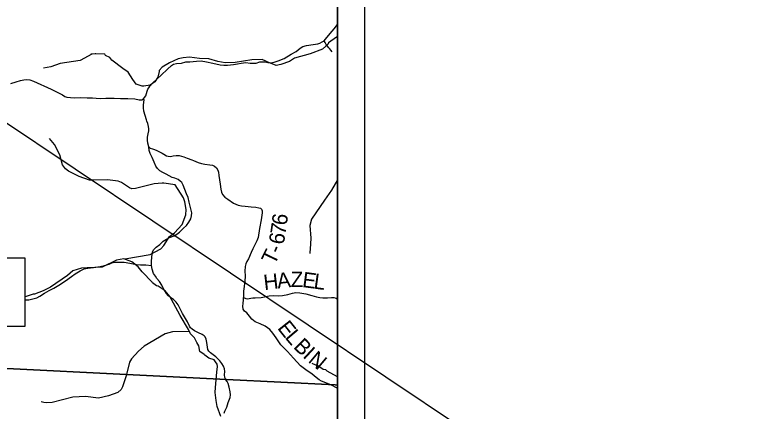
# Model space of a CAD drawing. Extents: x -1.8 to 75.7, y -2 to 25.
# Drawn here: x 7.704 to 10.399, y 16.93 to 18.399 of the extents above; entities that cross this region are included whole.
import ezdxf

# ---------------------------------------------------------------- set-up
doc = ezdxf.new("R2010")
doc.units = 0
for name, color, linetype in [('GM_X_County_Road', 7, 'Continuous'), ('GM_X_Minor_River', 7, 'Continuous'), ('GM_X_Township', 7, 'Continuous'), ('GM_X_Township_Road', 7, 'Continuous'), ('GM_X_Township_Road_Text', 7, 'Continuous'), ('SH_Data', 7, 'Continuous'), ('TX_P_1', 7, 'Continuous')]:
    doc.layers.add(name, color=color, linetype=linetype)

msp = doc.modelspace()

# ---------------------------------------------------------------- linework, layer by layer
at = {"layer": 'GM_X_County_Road'}
for points in [[(7.6901, 18.1441), (7.7101, 18.1505), (7.7266, 18.1554), (7.7386, 18.1583), (7.7495, 18.1594), (7.761, 18.1577), (7.774, 18.1524), (7.8395, 18.1227), (7.8649, 18.1103), (7.8814, 18.1017), (7.8905, 18.0962), (7.8982, 18.0935), (7.9118, 18.0918), (7.927, 18.0914), (7.95, 18.0925), (7.9735, 18.0912), (7.9924, 18.0916), (8.0071, 18.0897), (8.0216, 18.0889), (8.0419, 18.0895), (8.0599, 18.0893), (8.0732, 18.0896), (8.0962, 18.0887), (8.1235, 18.0882), (8.1497, 18.087), (8.1656, 18.0839), (8.1753, 18.0832), (8.1821, 18.0868), (8.186, 18.0917), (8.19, 18.0987), (8.1958, 18.1153), (8.1984, 18.1232), (8.2012, 18.1282), (8.2049, 18.1342), (8.2162, 18.1462), (8.247, 18.1755), (8.27, 18.1976), (8.2854, 18.2109), (8.2927, 18.2154), (8.3044, 18.2182), (8.3224, 18.22), (8.3383, 18.2238), (8.3538, 18.2243), (8.3779, 18.2273), (8.395, 18.2286), (8.4152, 18.2243), (8.4389, 18.2191), (8.466, 18.2135), (8.4791, 18.2118), (8.493, 18.2124), (8.5147, 18.2139), (8.5296, 18.2165), (8.5438, 18.2199), (8.5607, 18.2214), (8.5771, 18.2199), (8.5902, 18.2191), (8.5988, 18.22), (8.6125, 18.2242), (8.6213, 18.2249), (8.6314, 18.224), (8.6426, 18.2215), (8.6533, 18.2204), (8.6654, 18.2228), (8.6802, 18.2283), (8.7026, 18.2371), (8.729, 18.2522), (8.7464, 18.2629), (8.7616, 18.2754), (8.7715, 18.2812), (8.7849, 18.2849), (8.8094, 18.2881), (8.8276, 18.2913), (8.8349, 18.2935), (8.8433, 18.2978), (8.8508, 18.3023), (8.8554, 18.3078), (8.8725, 18.3289), (8.8874, 18.3469), (8.9, 18.3629)], [(8.2016, 17.9093), (8.1978, 17.9228), (8.1961, 17.934), (8.1971, 17.945), (8.1992, 17.9573), (8.2009, 17.9685), (8.2013, 17.9768), (8.2001, 17.9844), (8.1984, 17.9954), (8.1944, 18.0045), (8.1925, 18.0096), (8.1876, 18.0256), (8.1829, 18.0417), (8.1812, 18.0542), (8.1817, 18.0644), (8.1831, 18.075), (8.184, 18.0834), (8.1821, 18.0868)], [(8.2749, 17.3575), (8.2746, 17.3577), (8.2665, 17.3668), (8.2613, 17.3758), (8.2551, 17.3867), (8.2493, 17.3969), (8.2408, 17.4104), (8.2312, 17.4226), (8.2257, 17.4301), (8.2187, 17.4407), (8.2137, 17.4566), (8.2109, 17.4696), (8.2113, 17.4861), (8.2134, 17.5129), (8.2151, 17.5199), (8.2193, 17.528), (8.229, 17.5375), (8.2428, 17.5481), (8.2548, 17.5602), (8.2669, 17.568), (8.2785, 17.5736), (8.2955, 17.5805), (8.3047, 17.5857), (8.3153, 17.5937), (8.3302, 17.6082), (8.3404, 17.6186), (8.3501, 17.6306), (8.3567, 17.6424), (8.3596, 17.6535), (8.3605, 17.6656), (8.3562, 17.685), (8.3508, 17.7042), (8.3466, 17.7214), (8.3409, 17.736), (8.3352, 17.7514), (8.3292, 17.7676), (8.3231, 17.7772), (8.3171, 17.783), (8.3099, 17.7883), (8.2978, 17.7933), (8.2879, 17.7964), (8.2652, 17.8084), (8.2536, 17.8146), (8.2423, 17.821), (8.234, 17.829), (8.2274, 17.8382), (8.2208, 17.8522), (8.2137, 17.8699), (8.2063, 17.885), (8.2028, 17.8962), (8.2016, 17.9093)], [(8.4909, 17.0408), (8.4871, 17.0473), (8.4867, 17.0482), (8.483, 17.0558), (8.4819, 17.0647), (8.4823, 17.078), (8.4819, 17.0876), (8.4777, 17.0976), (8.4718, 17.1076), (8.4642, 17.1168), (8.4581, 17.1229), (8.4494, 17.1316), (8.4402, 17.1392), (8.4297, 17.1469), (8.4241, 17.1526), (8.4204, 17.1597), (8.4157, 17.185), (8.4136, 17.1975), (8.4103, 17.2059), (8.406, 17.2099), (8.3995, 17.2142), (8.3848, 17.221), (8.3707, 17.2284), (8.3613, 17.2349), (8.3554, 17.2398), (8.3517, 17.2459), (8.3452, 17.2613), (8.3375, 17.2744), (8.326, 17.2927), (8.3163, 17.3127), (8.3099, 17.3239), (8.3027, 17.3339), (8.2922, 17.3446), (8.2835, 17.3505), (8.2749, 17.3575)], [(8.4805, 16.9239), (8.483, 16.9311), (8.4901, 16.9459), (8.4956, 16.9631), (8.5021, 16.9818), (8.5034, 16.9917), (8.5021, 17.0026), (8.4991, 17.02), (8.4952, 17.0333), (8.4909, 17.0408)]]:
    msp.add_lwpolyline(points, dxfattribs=at)
at = {"layer": 'GM_X_Minor_River'}
for points in [[(8.9, 18.3201), (8.8962, 18.3152), (8.866, 18.2946), (8.8641, 18.2889), (8.8566, 18.2824), (8.8449, 18.2717), (8.7984, 18.2534), (8.7406, 18.2377), (8.7221, 18.2262), (8.6903, 18.2147), (8.6725, 18.2109), (8.6393, 18.2245), (8.6347, 18.2264), (8.6215, 18.2328), (8.5833, 18.232), (8.5217, 18.2219), (8.4843, 18.2203), (8.4574, 18.2252), (8.4242, 18.2354), (8.3886, 18.2372), (8.352, 18.2413), (8.3281, 18.2393), (8.31, 18.2359), (8.2775, 18.221), (8.2507, 18.205), (8.2397, 18.192), (8.2394, 18.1882), (8.2345, 18.1677), (8.2231, 18.1509), (8.2062, 18.1379), (8.1831, 18.1345), (8.1763, 18.1337), (8.1551, 18.1412), (8.1426, 18.1591), (8.1252, 18.186), (8.1048, 18.1993), (8.0647, 18.2311), (8.0567, 18.241), (8.0412, 18.2478), (8.0386, 18.2524), (8.0057, 18.2538), (8.0023, 18.2538), (7.9864, 18.2522)], [(7.9904, 18.2526), (7.9474, 18.2288), (7.8738, 18.2179), (7.839, 18.2057), (7.812, 18.2013)], [(8.113, 17.4943), (8.2062, 17.5104), (8.2454, 17.5315), (8.2567, 17.5441), (8.2782, 17.578), (8.2971, 17.591), (8.3248, 17.6217), (8.3388, 17.6577), (8.3394, 17.6774), (8.3349, 17.7057), (8.3297, 17.7202), (8.2991, 17.7691), (8.2565, 17.775), (8.2509, 17.7756), (8.2217, 17.7731), (8.1527, 17.7551), (8.1387, 17.7544), (8.1301, 17.7581), (8.0997, 17.777), (8.0874, 17.783), (8.0486, 17.7877), (7.996, 17.786), (7.9817, 17.786), (7.9435, 17.7998), (7.9041, 17.8189), (7.8926, 17.8276), (7.8821, 17.8435), (7.8726, 17.8803), (7.8522, 17.9178), (7.8344, 17.94)], [(8.9, 17.7875), (8.8772, 17.7491), (8.8512, 17.712), (8.8035, 17.6412), (8.798, 17.6188), (8.8016, 17.5709), (8.7987, 17.5302), (8.7979, 17.5196), (8.7971, 17.5146)], [(8.2924, 17.3311), (8.2792, 17.355), (8.2618, 17.3763), (8.2357, 17.3937), (8.2296, 17.3948), (8.2156, 17.4062), (8.2133, 17.4085), (8.177, 17.4464), (8.1619, 17.4646), (8.1384, 17.4843), (8.1085, 17.4953), (8.0821, 17.4903), (8.0288, 17.4635), (7.9729, 17.4611), (7.9521, 17.4603), (7.9207, 17.4504), (7.8999, 17.4332), (7.8372, 17.3905), (7.8104, 17.376), (7.7779, 17.3641), (7.7734, 17.3634), (7.7477, 17.3549), (7.7429, 17.3544)], [(8.4675, 16.9108), (8.4546, 16.9484), (8.4508, 16.9708), (8.447, 17.0004), (8.4481, 17.0187), (8.453, 17.0749), (8.4556, 17.0958), (8.4544, 17.1046), (8.4488, 17.1133), (8.4435, 17.1213), (8.4242, 17.1265), (8.4087, 17.1387), (8.4068, 17.141), (8.3905, 17.1512), (8.3871, 17.1721), (8.3788, 17.1854), (8.3704, 17.2024), (8.3557, 17.2176), (8.3481, 17.2328), (8.3174, 17.2856), (8.2924, 17.3311)], [(8.3514, 17.2263), (8.2892, 17.2251), (8.2615, 17.217), (8.1839, 17.1718), (8.1637, 17.1526), (8.1378, 17.125), (8.1301, 17.1121), (8.117, 17.062), (8.1039, 17.0214), (8.0985, 17.0104), (8.0871, 17.0003), (8.0521, 16.9872), (8.0146, 16.979), (7.9668, 16.9847), (7.9198, 16.9827), (7.8439, 16.9634), (7.823, 16.9617), (7.8124, 16.9625), (7.8034, 16.9652)], [(8.9, 17.0582), (8.8616, 17.0793), (8.8567, 17.0835), (8.8472, 17.085), (8.823, 17.1016), (8.82, 17.1009), (8.806, 17.1073)]]:
    msp.add_lwpolyline(points, dxfattribs=at)
at = {"layer": 'GM_X_Township'}
for points in [[(6.4874, 20.9), (6.4493, 20.1816), (6.4185, 19.6642), (6.3889, 19.1678), (6.3299, 18.1515), (6.3259, 18.1065), (6.3233, 18.0805), (6.3226, 18.0577), (6.3212, 18.0078), (6.3199, 17.9861), (6.252, 17.1543), (7.1962, 17.1121), (7.3049, 17.1072), (8.4894, 17.0481), (8.8908, 17.028), (8.9, 17.0276)], [(8.9, 17.0276), (8.9, 20.9), (6.4874, 20.9)], [(8.9, 17.0276), (8.8908, 17.028), (8.4894, 17.0481), (7.3049, 17.1072), (7.1962, 17.1121), (6.252, 17.1543), (6.2265, 16.7539), (6.1898, 16.179), (6.1707, 15.8638), (6.1259, 15.1242), (6.1136, 14.9242), (6.0891, 14.525), (6.0631, 14.1)], [(6.0631, 14.1), (8.9, 14.1), (8.9, 17.0276)]]:
    msp.add_lwpolyline(points, dxfattribs=at)
at = {"layer": 'GM_X_Township_Road'}
for points in [[(8.8801, 18.2614), (8.8756, 18.2679), (8.8713, 18.2724), (8.8682, 18.2765), (8.8626, 18.2829), (8.8581, 18.2891), (8.854, 18.2965), (8.8508, 18.3023)], [(8.2016, 17.9093), (8.2064, 17.9052), (8.2146, 17.9019), (8.2223, 17.8994), (8.2311, 17.8956), (8.2412, 17.8907), (8.2506, 17.886), (8.2571, 17.8822), (8.2674, 17.8768), (8.2733, 17.8755), (8.2815, 17.8742), (8.2912, 17.8766), (8.3021, 17.8781), (8.3132, 17.877), (8.331, 17.8723), (8.3428, 17.8682), (8.3603, 17.8618)], [(8.3603, 17.8618), (8.3669, 17.8594), (8.3836, 17.8521), (8.396, 17.8478), (8.4087, 17.8457), (8.4275, 17.8431), (8.4376, 17.8412), (8.4447, 17.8384), (8.4519, 17.8321), (8.4571, 17.8236), (8.4595, 17.8159), (8.4604, 17.8039), (8.4651, 17.7717), (8.4677, 17.7533), (8.4704, 17.7417), (8.4745, 17.7333), (8.4829, 17.7232), (8.4936, 17.7157), (8.5144, 17.7014), (8.532, 17.6941), (8.5451, 17.6906), (8.5584, 17.6898), (8.5805, 17.6876), (8.5976, 17.6859), (8.6085, 17.6842), (8.6152, 17.6821), (8.6184, 17.6793), (8.621, 17.6726), (8.6206, 17.6651), (8.6169, 17.6398), (8.6113, 17.6072), (8.606, 17.5735), (8.6017, 17.5611), (8.595, 17.5487), (8.5869, 17.5315), (8.5809, 17.5184), (8.5706, 17.4953), (8.5648, 17.4854), (8.5603, 17.4768), (8.5575, 17.4667), (8.5573, 17.4494), (8.5575, 17.432), (8.5566, 17.4112), (8.552, 17.3753), (8.5524, 17.3521), (8.5609, 17.3479), (8.5661, 17.3469), (8.586, 17.3503), (8.5946, 17.3507), (8.6169, 17.3512), (8.6467, 17.3582), (8.6615, 17.3589), (8.68, 17.3584), (8.6967, 17.3587), (8.7162, 17.3632), (8.7331, 17.3681), (8.746, 17.3696), (8.7603, 17.3689), (8.7829, 17.3648), (8.8053, 17.3589), (8.8222, 17.3537), (8.8339, 17.3518), (8.8461, 17.3507), (8.8625, 17.3507), (8.8775, 17.3518), (8.8865, 17.3512), (8.8944, 17.3486), (8.9, 17.3452)], [(7.7429, 17.3426), (7.7578, 17.3436), (7.7724, 17.3462), (7.7869, 17.3504), (7.7975, 17.3561), (7.815, 17.3679), (7.832, 17.3776), (7.8498, 17.3868), (7.868, 17.3972), (7.8935, 17.4138), (7.915, 17.4292), (7.9292, 17.4391), (7.9479, 17.4509), (7.9618, 17.4573), (7.9763, 17.4604), (7.9966, 17.4627), (8.0217, 17.4663), (8.0375, 17.4696), (8.0541, 17.4753), (8.0647, 17.48), (8.0758, 17.4819), (8.0959, 17.4831), (8.1096, 17.4821), (8.1307, 17.4783), (8.1562, 17.4741), (8.1706, 17.4729), (8.19, 17.4729), (8.2109, 17.4696)], [(8.8918, 17.0191), (8.8828, 17.0243), (8.8715, 17.029), (8.8623, 17.0329), (8.8409, 17.0419), (8.8319, 17.0468), (8.8212, 17.0554), (8.8057, 17.0675), (8.7833, 17.0834), (8.7631, 17.0982), (8.7368, 17.1266), (8.7154, 17.1519), (8.7034, 17.1634), (8.6904, 17.1758), (8.6729, 17.202), (8.6605, 17.2201), (8.65, 17.2328), (8.6319, 17.2451), (8.6132, 17.2539), (8.5951, 17.2617), (8.5833, 17.2717), (8.5736, 17.2831), (8.5637, 17.2943), (8.5552, 17.3009), (8.5504, 17.3085), (8.5495, 17.319), (8.5504, 17.3299), (8.5521, 17.343), (8.5524, 17.3521)], [(8.9, 17.0144), (8.8956, 17.0168), (8.8918, 17.0191)]]:
    msp.add_lwpolyline(points, dxfattribs=at)
at = {"layer": 'SH_Data'}
for p, q in [((9, 21), (9, 14)), ((8.9, 20.9), (8.9, 14.1))]:
    msp.add_line(p, q, dxfattribs=at)
at = {"layer": 'TX_P_1'}
msp.add_line((-1.8436, 24.3711), (37.5745, -2.0199), dxfattribs=at)
msp.add_lwpolyline([(6.4418, 17.499), (7.7429, 17.499), (7.7429, 17.2447), (6.4418, 17.2447)], close=True, dxfattribs=at)

# ---------------------------------------------------------------- texts
at = {"layer": 'GM_X_Township_Road_Text'}
for s, rotation, p in [('6', 82.0801, (8.7119, 17.6166)), ('7', 81.6652, (8.7068, 17.5815)), ('6', 79.5431, (8.7001, 17.5449)), ('T', 63.9936, (8.6668, 17.4694)), ('-', 66.381, (8.6866, 17.5099)), ('H', 6.6614, (8.6293, 17.3789)), ('A', 6.4943, (8.6789, 17.3847)), ('Z', 0.3086, (8.727, 17.3902)), ('E', 352.4981, (8.7674, 17.3906)), ('L', 352.2796, (8.8095, 17.385)), ('E', 308.4584, (8.6752, 17.238)), ('L', 310.3001, (8.7029, 17.2032)), ('B', 315.1923, (8.7339, 17.167)), ('I', 317.2544, (8.7686, 17.1326)), ('N', 320.1229, (8.7881, 17.1148))]:
    msp.add_text(s, height=0.0568, rotation=rotation, dxfattribs=at).set_placement(p)

doc.saveas('drawing.dxf')
